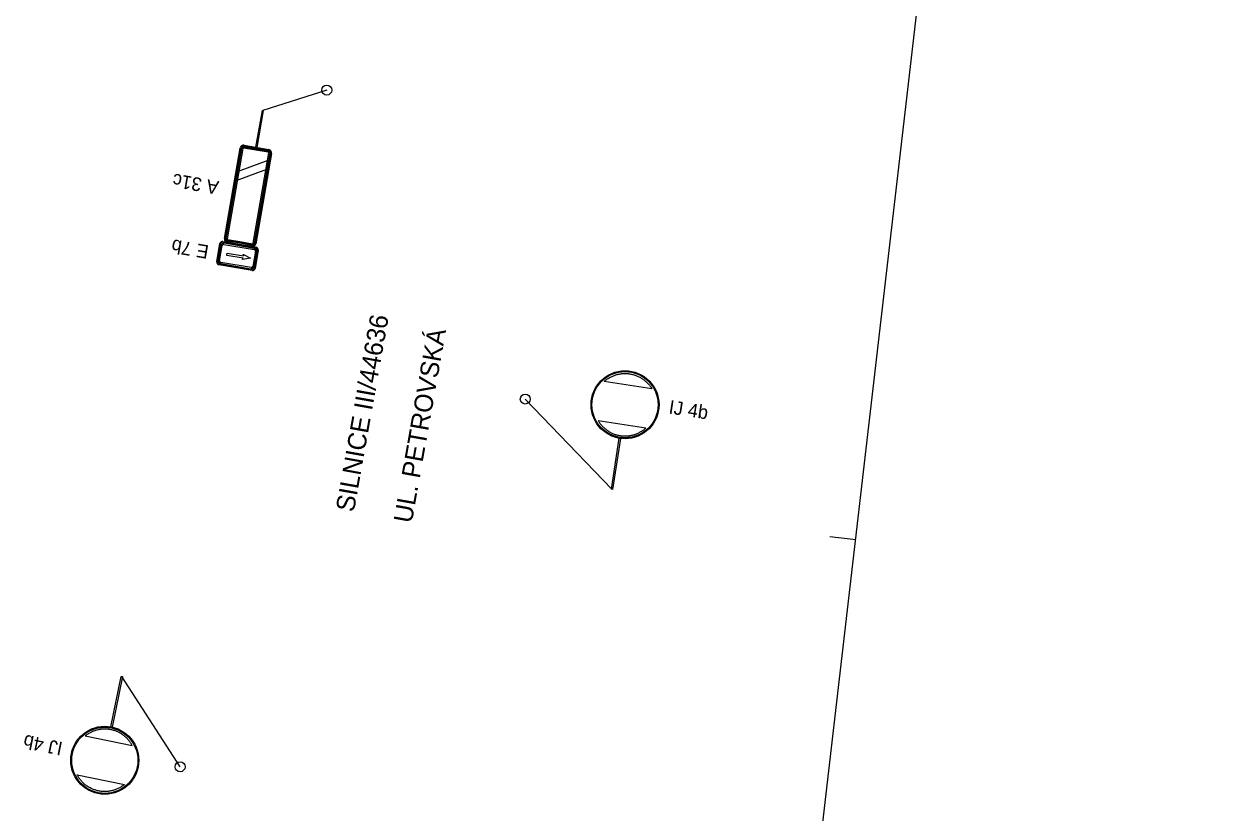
# Model space of a CAD drawing. Extents: x -559989 to -559846, y -1077380 to -1077158.
# Drawn here: x -559904.1 to -559845.9, y -1077341.1 to -1077303.1 of the extents above; entities that cross this region are included whole.
import ezdxf

# ---------------------------------------------------------------- set-up
doc = ezdxf.new("R2010")
doc.units = 0
for name, color, linetype in [('popis', 7, 'Continuous'), ('rozpiska_ramecek', 7, 'Continuous'), ('stavajici_znacky', 7, 'Continuous')]:
    doc.layers.add(name, color=color, linetype=linetype)

msp = doc.modelspace()

# ---------------------------------------------------------------- linework, layer by layer
at = {"layer": 'rozpiska_ramecek'}
for p, q in [((-559870.08, -1077380.087), (-559845.922, -1077171.481)), ((-559865.282, -1077327.791), (-559864.041, -1077327.935))]:
    msp.add_line(p, q, dxfattribs=at)
at = {"layer": 'stavajici_znacky'}
for p, q in [((-559889.519, -1077306.302), (-559892.601, -1077307.285)), ((-559894.453, -1077313.438), (-559893.695, -1077309.088)), ((-559894.4, -1077313.447), (-559893.642, -1077309.097)), ((-559894.372, -1077313.452), (-559893.615, -1077309.102)), ((-559893.561, -1077309.111), (-559894.319, -1077313.461)), ((-559892.339, -1077309.296), (-559893.528, -1077309.088)), ((-559893.519, -1077309.035), (-559892.329, -1077309.242)), ((-559893.514, -1077309.007), (-559892.324, -1077309.214)), ((-559893.505, -1077308.954), (-559892.315, -1077309.162)), ((-559893.779, -1077310.199), (-559892.345, -1077309.673)), ((-559893.073, -1077313.677), (-559892.316, -1077309.328)), ((-559892.262, -1077309.337), (-559893.02, -1077313.687)), ((-559892.235, -1077309.342), (-559892.992, -1077313.692)), ((-559892.182, -1077309.351), (-559892.94, -1077313.701)), ((-559892.345, -1077309.673), (-559892.425, -1077310.129)), ((-559892.425, -1077310.129), (-559893.858, -1077310.654)), ((-559893.858, -1077310.654), (-559893.779, -1077310.199)), ((-559894.818, -1077314.565), (-559894.666, -1077313.691)), ((-559894.787, -1077314.57), (-559894.635, -1077313.696)), ((-559894.61, -1077313.781), (-559894.735, -1077314.501)), ((-559894.681, -1077314.514), (-559894.554, -1077313.786)), ((-559894.526, -1077313.623), (-559892.933, -1077313.9)), ((-559894.521, -1077313.592), (-559892.927, -1077313.869)), ((-559894.473, -1077313.73), (-559893.018, -1077313.983)), ((-559893.012, -1077313.928), (-559894.461, -1077313.676)), ((-559893.115, -1077313.754), (-559893.71, -1077313.651)), ((-559893.701, -1077313.597), (-559893.106, -1077313.7)), ((-559894.338, -1077314.261), (-559894.321, -1077314.155)), ((-559893.541, -1077314.393), (-559894.338, -1077314.261)), ((-559894.321, -1077314.155), (-559893.524, -1077314.287)), ((-559893.586, -1077314.446), (-559893.541, -1077314.393)), ((-559893.202, -1077314.398), (-559893.575, -1077314.46)), ((-559893.549, -1077314.214), (-559893.548, -1077314.213)), ((-559893.549, -1077314.215), (-559893.549, -1077314.214)), ((-559893.549, -1077314.216), (-559893.549, -1077314.215)), ((-559893.549, -1077314.215), (-559893.549, -1077314.215)), ((-559893.549, -1077314.217), (-559893.549, -1077314.216)), ((-559893.549, -1077314.218), (-559893.549, -1077314.217)), ((-559893.549, -1077314.219), (-559893.549, -1077314.218)), ((-559893.549, -1077314.22), (-559893.549, -1077314.219)), ((-559893.548, -1077314.221), (-559893.549, -1077314.22)), ((-559893.548, -1077314.213), (-559893.547, -1077314.212)), ((-559893.548, -1077314.213), (-559893.548, -1077314.213)), ((-559893.524, -1077314.287), (-559893.548, -1077314.221)), ((-559893.547, -1077314.212), (-559893.546, -1077314.211)), ((-559893.547, -1077314.212), (-559893.547, -1077314.212)), ((-559893.546, -1077314.211), (-559893.545, -1077314.211)), ((-559893.545, -1077314.211), (-559893.543, -1077314.21)), ((-559893.543, -1077314.21), (-559893.542, -1077314.21)), ((-559893.542, -1077314.21), (-559893.54, -1077314.209)), ((-559893.54, -1077314.209), (-559893.539, -1077314.209)), ((-559893.539, -1077314.209), (-559893.538, -1077314.21)), ((-559893.538, -1077314.21), (-559893.536, -1077314.21)), ((-559893.536, -1077314.21), (-559893.535, -1077314.21)), ((-559893.535, -1077314.21), (-559893.534, -1077314.21)), ((-559893.534, -1077314.21), (-559893.201, -1077314.391)), ((-559893.201, -1077314.391), (-559893.202, -1077314.392)), ((-559893.202, -1077314.392), (-559893.202, -1077314.395)), ((-559893.202, -1077314.395), (-559893.202, -1077314.397)), ((-559893.202, -1077314.397), (-559893.202, -1077314.398)), ((-559892.96, -1077314.053), (-559893.088, -1077314.792)), ((-559893.033, -1077314.797), (-559892.908, -1077314.078)), ((-559892.855, -1077314.006), (-559893.007, -1077314.88)), ((-559892.824, -1077314.011), (-559892.977, -1077314.886)), ((-559892.961, -1077314.064), (-559892.96, -1077314.053)), ((-559893.121, -1077314.984), (-559894.715, -1077314.707)), ((-559893.116, -1077314.954), (-559894.709, -1077314.676)), ((-559894.631, -1077314.65), (-559893.181, -1077314.902)), ((-559893.169, -1077314.848), (-559894.624, -1077314.595)), ((-559893.587, -1077314.449), (-559893.586, -1077314.447)), ((-559893.587, -1077314.45), (-559893.587, -1077314.449)), ((-559893.587, -1077314.451), (-559893.587, -1077314.45)), ((-559893.587, -1077314.452), (-559893.587, -1077314.451)), ((-559893.587, -1077314.454), (-559893.587, -1077314.452)), ((-559893.587, -1077314.455), (-559893.587, -1077314.454)), ((-559893.586, -1077314.456), (-559893.587, -1077314.455)), ((-559893.586, -1077314.447), (-559893.586, -1077314.446)), ((-559893.585, -1077314.457), (-559893.586, -1077314.456)), ((-559893.584, -1077314.458), (-559893.585, -1077314.457)), ((-559893.583, -1077314.459), (-559893.584, -1077314.458)), ((-559893.582, -1077314.459), (-559893.583, -1077314.459)), ((-559893.581, -1077314.46), (-559893.582, -1077314.459)), ((-559893.58, -1077314.46), (-559893.581, -1077314.46)), ((-559893.581, -1077314.46), (-559893.581, -1077314.46)), ((-559893.579, -1077314.46), (-559893.58, -1077314.46)), ((-559893.578, -1077314.46), (-559893.579, -1077314.46)), ((-559893.577, -1077314.46), (-559893.578, -1077314.46)), ((-559893.576, -1077314.46), (-559893.577, -1077314.46)), ((-559893.575, -1077314.46), (-559893.576, -1077314.46)), ((-559876.09, -1077320.273), (-559876.058, -1077320.248)), ((-559876.058, -1077320.248), (-559876.025, -1077320.225)), ((-559876.025, -1077320.225), (-559875.992, -1077320.202)), ((-559875.992, -1077320.202), (-559875.958, -1077320.179)), ((-559875.958, -1077320.179), (-559875.923, -1077320.158)), ((-559875.923, -1077320.158), (-559875.888, -1077320.138)), ((-559875.888, -1077320.138), (-559875.852, -1077320.118)), ((-559875.852, -1077320.118), (-559875.816, -1077320.1)), ((-559875.816, -1077320.1), (-559875.779, -1077320.082)), ((-559875.779, -1077320.082), (-559875.742, -1077320.066)), ((-559875.742, -1077320.066), (-559875.705, -1077320.05)), ((-559875.705, -1077320.05), (-559875.666, -1077320.036)), ((-559875.666, -1077320.036), (-559875.628, -1077320.022)), ((-559875.628, -1077320.022), (-559875.589, -1077320.01)), ((-559875.589, -1077320.01), (-559875.549, -1077319.998)), ((-559875.549, -1077319.998), (-559875.51, -1077319.988)), ((-559875.51, -1077319.988), (-559875.47, -1077319.979)), ((-559875.47, -1077319.979), (-559875.429, -1077319.97)), ((-559875.429, -1077319.97), (-559875.388, -1077319.963)), ((-559875.388, -1077319.963), (-559875.347, -1077319.957)), ((-559875.347, -1077319.957), (-559875.306, -1077319.953)), ((-559875.306, -1077319.953), (-559875.264, -1077319.949)), ((-559875.264, -1077319.949), (-559875.222, -1077319.946)), ((-559875.222, -1077319.946), (-559875.18, -1077319.945)), ((-559875.18, -1077319.945), (-559875.138, -1077319.945)), ((-559875.138, -1077319.945), (-559875.095, -1077319.946)), ((-559875.095, -1077319.946), (-559875.053, -1077319.948)), ((-559875.053, -1077319.948), (-559875.01, -1077319.952)), ((-559875.01, -1077319.952), (-559874.967, -1077319.956)), ((-559874.967, -1077319.956), (-559874.924, -1077319.962)), ((-559874.924, -1077319.962), (-559874.881, -1077319.97)), ((-559874.881, -1077319.97), (-559874.839, -1077319.978)), ((-559874.839, -1077319.978), (-559874.797, -1077319.988)), ((-559874.797, -1077319.988), (-559874.756, -1077319.998)), ((-559874.756, -1077319.998), (-559874.715, -1077320.01)), ((-559874.715, -1077320.01), (-559874.675, -1077320.023)), ((-559874.675, -1077320.023), (-559874.635, -1077320.037)), ((-559874.635, -1077320.037), (-559874.596, -1077320.052)), ((-559874.596, -1077320.052), (-559874.557, -1077320.068)), ((-559874.557, -1077320.068), (-559874.519, -1077320.085)), ((-559874.519, -1077320.085), (-559874.482, -1077320.103)), ((-559874.482, -1077320.103), (-559874.445, -1077320.122)), ((-559874.445, -1077320.122), (-559874.409, -1077320.142)), ((-559874.409, -1077320.142), (-559874.374, -1077320.163)), ((-559874.374, -1077320.163), (-559874.339, -1077320.185)), ((-559874.339, -1077320.185), (-559874.305, -1077320.208)), ((-559874.305, -1077320.208), (-559874.272, -1077320.231)), ((-559874.272, -1077320.231), (-559874.239, -1077320.256)), ((-559874.239, -1077320.256), (-559874.207, -1077320.281)), ((-559876.152, -1077320.325), (-559876.121, -1077320.299)), ((-559873.863, -1077320.678), (-559876.152, -1077320.325)), ((-559876.121, -1077320.299), (-559876.09, -1077320.273)), ((-559874.207, -1077320.281), (-559874.176, -1077320.307)), ((-559874.176, -1077320.307), (-559874.145, -1077320.334)), ((-559874.145, -1077320.334), (-559874.116, -1077320.362)), ((-559874.116, -1077320.362), (-559874.087, -1077320.391)), ((-559874.087, -1077320.391), (-559874.058, -1077320.42)), ((-559874.058, -1077320.42), (-559874.031, -1077320.45)), ((-559874.031, -1077320.45), (-559874.005, -1077320.48)), ((-559874.005, -1077320.48), (-559873.979, -1077320.512)), ((-559873.979, -1077320.512), (-559873.954, -1077320.544)), ((-559873.954, -1077320.544), (-559873.93, -1077320.577)), ((-559873.93, -1077320.577), (-559873.907, -1077320.61)), ((-559873.907, -1077320.61), (-559873.885, -1077320.644)), ((-559873.885, -1077320.644), (-559873.863, -1077320.678)), ((-559879.96, -1077321.177), (-559875.782, -1077325.52)), ((-559876.444, -1077322.219), (-559876.423, -1077322.254)), ((-559874.156, -1077322.573), (-559876.444, -1077322.219)), ((-559876.423, -1077322.254), (-559876.401, -1077322.288)), ((-559876.401, -1077322.288), (-559876.378, -1077322.321)), ((-559876.378, -1077322.321), (-559876.354, -1077322.354)), ((-559876.354, -1077322.354), (-559876.329, -1077322.386)), ((-559876.329, -1077322.386), (-559876.303, -1077322.417)), ((-559876.303, -1077322.417), (-559876.277, -1077322.448)), ((-559876.277, -1077322.448), (-559876.249, -1077322.478)), ((-559876.249, -1077322.478), (-559876.221, -1077322.507)), ((-559876.221, -1077322.507), (-559876.192, -1077322.536)), ((-559876.192, -1077322.536), (-559876.163, -1077322.563)), ((-559876.163, -1077322.563), (-559876.132, -1077322.59)), ((-559874.187, -1077322.599), (-559874.156, -1077322.573)), ((-559876.132, -1077322.59), (-559876.101, -1077322.616)), ((-559876.101, -1077322.616), (-559876.069, -1077322.642)), ((-559876.069, -1077322.642), (-559876.036, -1077322.666)), ((-559876.036, -1077322.666), (-559876.003, -1077322.69)), ((-559876.003, -1077322.69), (-559875.968, -1077322.713)), ((-559875.968, -1077322.713), (-559875.934, -1077322.735)), ((-559875.934, -1077322.735), (-559875.898, -1077322.756)), ((-559875.898, -1077322.756), (-559875.862, -1077322.776)), ((-559875.862, -1077322.776), (-559875.825, -1077322.795)), ((-559875.825, -1077322.795), (-559875.788, -1077322.813)), ((-559875.788, -1077322.813), (-559875.75, -1077322.83)), ((-559875.75, -1077322.83), (-559875.712, -1077322.846)), ((-559875.712, -1077322.846), (-559875.672, -1077322.861)), ((-559875.672, -1077322.861), (-559875.633, -1077322.875)), ((-559875.633, -1077322.875), (-559875.592, -1077322.888)), ((-559875.592, -1077322.888), (-559875.551, -1077322.9)), ((-559875.551, -1077322.9), (-559875.51, -1077322.91)), ((-559875.51, -1077322.91), (-559875.468, -1077322.92)), ((-559875.468, -1077322.92), (-559875.426, -1077322.928)), ((-559875.426, -1077322.928), (-559875.383, -1077322.935)), ((-559875.383, -1077322.935), (-559875.34, -1077322.941)), ((-559875.34, -1077322.941), (-559875.297, -1077322.946)), ((-559875.297, -1077322.946), (-559875.254, -1077322.95)), ((-559875.254, -1077322.95), (-559875.212, -1077322.952)), ((-559875.212, -1077322.952), (-559875.169, -1077322.953)), ((-559875.169, -1077322.953), (-559875.127, -1077322.953)), ((-559875.127, -1077322.953), (-559875.085, -1077322.952)), ((-559875.085, -1077322.952), (-559875.043, -1077322.949)), ((-559875.043, -1077322.949), (-559875.002, -1077322.945)), ((-559875.002, -1077322.945), (-559874.96, -1077322.941)), ((-559874.96, -1077322.941), (-559874.919, -1077322.935)), ((-559874.919, -1077322.935), (-559874.878, -1077322.928)), ((-559874.878, -1077322.928), (-559874.838, -1077322.919)), ((-559874.838, -1077322.919), (-559874.798, -1077322.91)), ((-559874.798, -1077322.91), (-559874.758, -1077322.9)), ((-559874.758, -1077322.9), (-559874.719, -1077322.888)), ((-559874.719, -1077322.888), (-559874.68, -1077322.876)), ((-559874.68, -1077322.876), (-559874.641, -1077322.862)), ((-559874.641, -1077322.862), (-559874.603, -1077322.848)), ((-559874.603, -1077322.848), (-559874.566, -1077322.832)), ((-559874.566, -1077322.832), (-559874.528, -1077322.816)), ((-559874.528, -1077322.816), (-559874.492, -1077322.798)), ((-559874.492, -1077322.798), (-559874.456, -1077322.78)), ((-559874.456, -1077322.78), (-559874.42, -1077322.761)), ((-559874.42, -1077322.761), (-559874.385, -1077322.74)), ((-559874.385, -1077322.74), (-559874.35, -1077322.719)), ((-559874.35, -1077322.719), (-559874.316, -1077322.697)), ((-559874.316, -1077322.697), (-559874.283, -1077322.674)), ((-559874.283, -1077322.674), (-559874.25, -1077322.65)), ((-559874.25, -1077322.65), (-559874.218, -1077322.625)), ((-559874.218, -1077322.625), (-559874.187, -1077322.599)), ((-559896.584, -1077338.881), (-559899.392, -1077334.534)), ((-559900.619, -1077337.122), (-559900.658, -1077337.133)), ((-559900.58, -1077337.111), (-559900.619, -1077337.122)), ((-559900.54, -1077337.101), (-559900.58, -1077337.111)), ((-559900.5, -1077337.093), (-559900.54, -1077337.101)), ((-559900.459, -1077337.086), (-559900.5, -1077337.093)), ((-559900.419, -1077337.079), (-559900.459, -1077337.086)), ((-559900.377, -1077337.074), (-559900.419, -1077337.079)), ((-559900.336, -1077337.07), (-559900.377, -1077337.074)), ((-559900.295, -1077337.067), (-559900.336, -1077337.07)), ((-559900.253, -1077337.066), (-559900.295, -1077337.067)), ((-559900.211, -1077337.065), (-559900.253, -1077337.066)), ((-559900.169, -1077337.066), (-559900.211, -1077337.065)), ((-559900.127, -1077337.068), (-559900.169, -1077337.066)), ((-559900.084, -1077337.071), (-559900.127, -1077337.068)), ((-559900.042, -1077337.075), (-559900.084, -1077337.071)), ((-559899.999, -1077337.081), (-559900.042, -1077337.075)), ((-559899.957, -1077337.088), (-559899.999, -1077337.081)), ((-559899.914, -1077337.096), (-559899.957, -1077337.088)), ((-559899.872, -1077337.105), (-559899.914, -1077337.096)), ((-559899.83, -1077337.116), (-559899.872, -1077337.105)), ((-559899.788, -1077337.127), (-559899.83, -1077337.116)), ((-559899.748, -1077337.14), (-559899.788, -1077337.127)), ((-559901.125, -1077337.374), (-559901.157, -1077337.399)), ((-559901.157, -1077337.399), (-559898.889, -1077337.862)), ((-559901.093, -1077337.35), (-559901.125, -1077337.374)), ((-559901.059, -1077337.327), (-559901.093, -1077337.35)), ((-559901.026, -1077337.304), (-559901.059, -1077337.327)), ((-559900.991, -1077337.283), (-559901.026, -1077337.304)), ((-559900.956, -1077337.262), (-559900.991, -1077337.283)), ((-559900.921, -1077337.243), (-559900.956, -1077337.262)), ((-559900.885, -1077337.224), (-559900.921, -1077337.243)), ((-559900.848, -1077337.207), (-559900.885, -1077337.224)), ((-559900.811, -1077337.19), (-559900.848, -1077337.207)), ((-559900.774, -1077337.174), (-559900.811, -1077337.19)), ((-559900.736, -1077337.159), (-559900.774, -1077337.174)), ((-559900.697, -1077337.146), (-559900.736, -1077337.159)), ((-559900.658, -1077337.133), (-559900.697, -1077337.146)), ((-559899.707, -1077337.153), (-559899.748, -1077337.14)), ((-559899.668, -1077337.168), (-559899.707, -1077337.153)), ((-559899.629, -1077337.184), (-559899.668, -1077337.168)), ((-559899.59, -1077337.201), (-559899.629, -1077337.184)), ((-559899.553, -1077337.219), (-559899.59, -1077337.201)), ((-559899.516, -1077337.238), (-559899.553, -1077337.219)), ((-559899.479, -1077337.258), (-559899.516, -1077337.238)), ((-559899.443, -1077337.279), (-559899.479, -1077337.258)), ((-559899.408, -1077337.3), (-559899.443, -1077337.279)), ((-559899.374, -1077337.323), (-559899.408, -1077337.3)), ((-559899.34, -1077337.346), (-559899.374, -1077337.323)), ((-559899.307, -1077337.371), (-559899.34, -1077337.346)), ((-559899.275, -1077337.396), (-559899.307, -1077337.371)), ((-559899.243, -1077337.422), (-559899.275, -1077337.396)), ((-559899.213, -1077337.449), (-559899.243, -1077337.422)), ((-559899.183, -1077337.476), (-559899.213, -1077337.449)), ((-559899.153, -1077337.505), (-559899.183, -1077337.476)), ((-559899.125, -1077337.534), (-559899.153, -1077337.505)), ((-559899.098, -1077337.564), (-559899.125, -1077337.534)), ((-559899.071, -1077337.595), (-559899.098, -1077337.564)), ((-559899.045, -1077337.626), (-559899.071, -1077337.595)), ((-559899.02, -1077337.658), (-559899.045, -1077337.626)), ((-559898.996, -1077337.69), (-559899.02, -1077337.658)), ((-559898.973, -1077337.724), (-559898.996, -1077337.69)), ((-559898.95, -1077337.757), (-559898.973, -1077337.724)), ((-559898.929, -1077337.792), (-559898.95, -1077337.757)), ((-559898.908, -1077337.827), (-559898.929, -1077337.792)), ((-559898.889, -1077337.862), (-559898.908, -1077337.827)), ((-559901.521, -1077339.313), (-559901.54, -1077339.277)), ((-559901.54, -1077339.277), (-559899.272, -1077339.74)), ((-559901.5, -1077339.348), (-559901.521, -1077339.313)), ((-559901.479, -1077339.382), (-559901.5, -1077339.348)), ((-559901.456, -1077339.416), (-559901.479, -1077339.382)), ((-559901.433, -1077339.449), (-559901.456, -1077339.416)), ((-559901.409, -1077339.482), (-559901.433, -1077339.449)), ((-559901.384, -1077339.514), (-559901.409, -1077339.482)), ((-559901.358, -1077339.545), (-559901.384, -1077339.514)), ((-559901.331, -1077339.575), (-559901.358, -1077339.545)), ((-559901.304, -1077339.605), (-559901.331, -1077339.575)), ((-559901.275, -1077339.634), (-559901.304, -1077339.605)), ((-559901.246, -1077339.663), (-559901.275, -1077339.634)), ((-559901.216, -1077339.691), (-559901.246, -1077339.663)), ((-559901.186, -1077339.717), (-559901.216, -1077339.691)), ((-559901.154, -1077339.743), (-559901.186, -1077339.717)), ((-559901.122, -1077339.768), (-559901.154, -1077339.743)), ((-559901.089, -1077339.793), (-559901.122, -1077339.768)), ((-559901.055, -1077339.816), (-559901.089, -1077339.793)), ((-559901.021, -1077339.839), (-559901.055, -1077339.816)), ((-559900.986, -1077339.861), (-559901.021, -1077339.839)), ((-559900.95, -1077339.882), (-559900.986, -1077339.861)), ((-559900.914, -1077339.901), (-559900.95, -1077339.882)), ((-559900.877, -1077339.92), (-559900.914, -1077339.901)), ((-559900.839, -1077339.938), (-559900.877, -1077339.92)), ((-559900.8, -1077339.955), (-559900.839, -1077339.938)), ((-559900.761, -1077339.971), (-559900.8, -1077339.955)), ((-559900.722, -1077339.986), (-559900.761, -1077339.971)), ((-559900.682, -1077339.999), (-559900.722, -1077339.986)), ((-559900.641, -1077340.012), (-559900.682, -1077339.999)), ((-559900.6, -1077340.024), (-559900.641, -1077340.012)), ((-559900.558, -1077340.034), (-559900.6, -1077340.024)), ((-559900.515, -1077340.043), (-559900.558, -1077340.034)), ((-559899.849, -1077340.028), (-559899.889, -1077340.038)), ((-559899.81, -1077340.017), (-559899.849, -1077340.028)), ((-559899.77, -1077340.006), (-559899.81, -1077340.017)), ((-559899.732, -1077339.993), (-559899.77, -1077340.006)), ((-559899.693, -1077339.98), (-559899.732, -1077339.993)), ((-559899.655, -1077339.965), (-559899.693, -1077339.98)), ((-559899.618, -1077339.949), (-559899.655, -1077339.965)), ((-559899.581, -1077339.932), (-559899.618, -1077339.949)), ((-559899.544, -1077339.915), (-559899.581, -1077339.932)), ((-559899.508, -1077339.896), (-559899.544, -1077339.915)), ((-559899.473, -1077339.876), (-559899.508, -1077339.896)), ((-559899.437, -1077339.856), (-559899.473, -1077339.876)), ((-559899.403, -1077339.834), (-559899.437, -1077339.856)), ((-559899.369, -1077339.812), (-559899.403, -1077339.834)), ((-559899.336, -1077339.789), (-559899.369, -1077339.812)), ((-559899.304, -1077339.765), (-559899.336, -1077339.789)), ((-559899.272, -1077339.74), (-559899.304, -1077339.765)), ((-559900.473, -1077340.051), (-559900.515, -1077340.043)), ((-559900.43, -1077340.058), (-559900.473, -1077340.051)), ((-559900.387, -1077340.064), (-559900.43, -1077340.058)), ((-559900.345, -1077340.068), (-559900.387, -1077340.064)), ((-559900.303, -1077340.071), (-559900.345, -1077340.068)), ((-559900.26, -1077340.073), (-559900.303, -1077340.071)), ((-559900.218, -1077340.074), (-559900.26, -1077340.073)), ((-559900.176, -1077340.073), (-559900.218, -1077340.074)), ((-559900.135, -1077340.071), (-559900.176, -1077340.073)), ((-559900.093, -1077340.069), (-559900.135, -1077340.071)), ((-559900.052, -1077340.065), (-559900.093, -1077340.069)), ((-559900.011, -1077340.06), (-559900.052, -1077340.065)), ((-559899.97, -1077340.053), (-559900.011, -1077340.06)), ((-559899.929, -1077340.046), (-559899.97, -1077340.053)), ((-559899.889, -1077340.038), (-559899.929, -1077340.046))]:
    msp.add_line(p, q, dxfattribs=at)
for points in [[(-559892.93, -1077309.055), (-559892.621, -1077307.281), (-559892.582, -1077307.288), (-559892.89, -1077309.062)], [(-559875.376, -1077323.072), (-559875.755, -1077325.524), (-559875.809, -1077325.515), (-559875.431, -1077323.063)], [(-559899.915, -1077336.959), (-559899.419, -1077334.528), (-559899.365, -1077334.539), (-559899.861, -1077336.97)]]:
    msp.add_lwpolyline(points, close=True, dxfattribs=at)
for points in [[(-559893.129, -1077313.834), (-559893.724, -1077313.731), (-559894.319, -1077313.627)], [(-559893.12, -1077313.782), (-559893.715, -1077313.678), (-559894.31, -1077313.575)], [(-559893.71, -1077313.651), (-559894.305, -1077313.547)], [(-559894.296, -1077313.494), (-559893.701, -1077313.597)]]:
    msp.add_lwpolyline(points, dxfattribs=at)
for centre, radius in [((-559889.519, -1077306.302), 0.239), ((-559875.154, -1077321.449), 1.638), ((-559875.154, -1077321.449), 1.593), ((-559879.96, -1077321.177), 0.239), ((-559900.214, -1077338.57), 1.638), ((-559900.214, -1077338.57), 1.593), ((-559896.584, -1077338.881), 0.239)]:
    msp.add_circle(centre, radius, dxfattribs=at)
for centre, radius, start, end in [((-559893.533, -1077309.116), 0.164, 80.10977, 170.11722), ((-559893.533, -1077309.116), 0.11, 80.10977, 170.11722), ((-559893.533, -1077309.116), 0.0825, 80.10977, 170.11722), ((-559893.533, -1077309.116), 0.0279, 80.10977, 170.11722), ((-559892.343, -1077309.323), 0.164, 350.11955, 80.10978), ((-559892.343, -1077309.323), 0.0279, 350.11955, 80.10977), ((-559892.343, -1077309.323), 0.0825, 350.11955, 80.10978), ((-559892.343, -1077309.323), 0.11, 350.11955, 80.10978), ((-559894.543, -1077313.715), 0.125, 79.8236, 168.65664), ((-559894.542, -1077313.715), 0.0945, 79.88719, 167.99841), ((-559894.481, -1077313.805), 0.13, 81.11985, 169.54042), ((-559894.482, -1077313.805), 0.0752, 83.77095, 165.99352), ((-559894.291, -1077313.466), 0.164, 170.11722, 260.17053), ((-559894.291, -1077313.466), 0.11, 170.11722, 260.17053), ((-559894.291, -1077313.466), 0.0825, 170.11722, 260.17053), ((-559894.291, -1077313.466), 0.0279, 170.11722, 260.17053), ((-559893.101, -1077313.673), 0.164, 260.13575, 350.11955), ((-559893.101, -1077313.673), 0.11, 260.13575, 350.11955), ((-559893.101, -1077313.673), 0.0825, 260.13575, 350.11955), ((-559893.101, -1077313.673), 0.0279, 260.13576, 350.11955), ((-559893.036, -1077314.056), 0.0752, 354.25005, 76.47262), ((-559893.036, -1077314.056), 0.13, 350.70315, 79.12371), ((-559892.948, -1077313.993), 0.0945, 352.24516, 80.35639), ((-559892.948, -1077313.993), 0.125, 351.58693, 80.41996), ((-559894.694, -1077314.583), 0.125, 171.58693, 260.41996), ((-559894.694, -1077314.583), 0.0945, 172.24516, 260.35639), ((-559894.606, -1077314.522), 0.13, 170.70315, 259.12371), ((-559894.606, -1077314.522), 0.0752, 174.25005, 256.47262), ((-559893.161, -1077314.773), 0.13, 261.11985, 349.54042), ((-559893.161, -1077314.774), 0.0752, 263.77095, 345.99352), ((-559893.099, -1077314.861), 0.125, 259.8236, 348.65664), ((-559893.1, -1077314.861), 0.0945, 259.88719, 347.99841)]:
    msp.add_arc(centre, radius, start, end, dxfattribs=at)

# ---------------------------------------------------------------- texts
at = {"layer": 'popis'}
for s, p in [('SILNICE III/44636', (-559888.215, -1077326.651)), ('UL. PETROVSKÁ', (-559885.43, -1077327.185))]:
    msp.add_text(s, height=0.891, rotation=79.90223, dxfattribs=at).set_placement(p)
at = {"layer": 'stavajici_znacky'}
for s, rotation, p in [('A 31c', 170.12179, (-559894.682, -1077310.693)), ('E 7b', 170.12179, (-559895.167, -1077313.786)), ('IJ 4b', 351.22438, (-559873.075, -1077321.868)), ('IJ 4b', 168.46997, (-559902.202, -1077337.705))]:
    msp.add_text(s, height=0.6533, rotation=rotation, dxfattribs=at).set_placement(p)

doc.saveas('drawing.dxf')
